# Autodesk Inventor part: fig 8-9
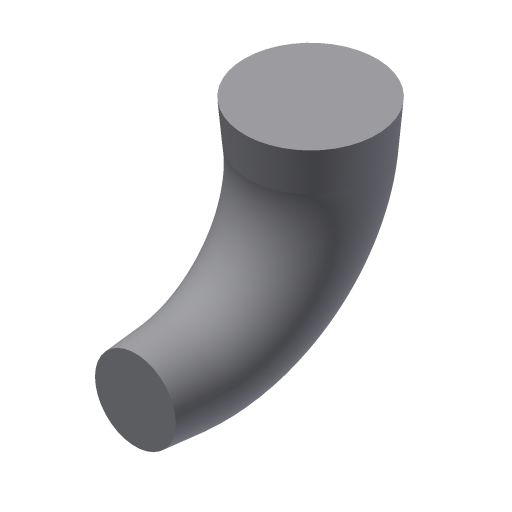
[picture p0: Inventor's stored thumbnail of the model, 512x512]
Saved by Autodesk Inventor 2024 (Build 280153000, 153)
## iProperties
Shininess: 77.0
Length Units: 11269
Angle Units: 11279
Time Units: 11290
Mass Units: 11283
Length Display Precision: 3
Angle Display Precision: 2
Created: 2001-12
Part Number: fig 8-9
Document SubType Name: Modeling
Designer: CADSoft
Density: 1 g/cm^3
Material: Generic
Appearance: Default
Density: 0.0
Volumn: 0.0
Area: 0.0
PropertySet Name: Model Information
Control State: 0
Master: False
Checked Out: False
Author: CADSoft
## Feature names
1. Sweep7
## Parameters: d4 = 15 mm, d5 = 15 mm, d13 = 5 deg, d14 = 0
